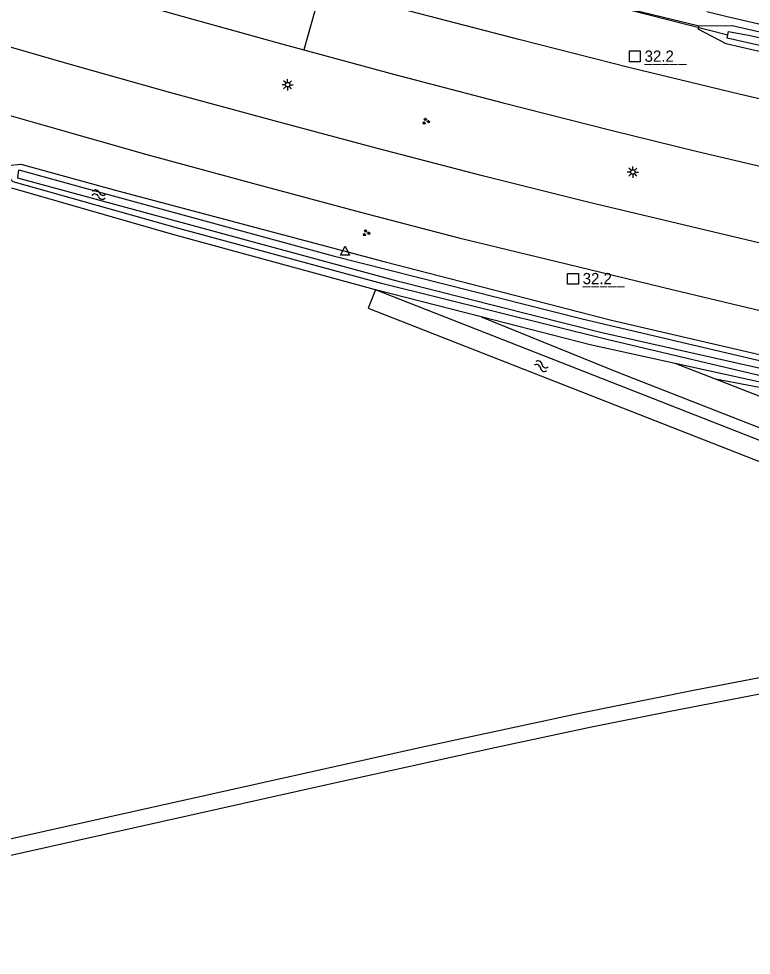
# Model space of a CAD drawing. Extents: x 130998 to 133001, y 398999 to 403002.
# Drawn here: x 131607.2 to 131688.7, y 400571.1 to 400675.3 of the extents above; entities that cross this region are included whole.
import ezdxf

# ---------------------------------------------------------------- set-up
doc = ezdxf.new("R2010")
doc.units = 0
for name, color, linetype in [('gg-afsc-hekwerk', 7, 'Continuous'), ('gg-knt-onverhard', 7, 'Continuous'), ('gg-knt-verharding', 7, 'Continuous'), ('gg-kntw-bovenkant insteek waterloop', 7, 'Continuous'), ('gg-kntw-waterlijn', 7, 'Continuous'), ('gg-kwrk-duiker nz buis', 7, 'Continuous'), ('gt-anno-nummer hm paal', 7, 'Continuous'), ('gt-grn-groengrens', 7, 'Continuous'), ('gt-grn-weggrens', 7, 'Continuous'), ('gt-symb-groenvak', 7, 'Continuous'), ('gt-symb-hm paal', 7, 'Continuous'), ('gt-symb-lichtmast', 7, 'Continuous'), ('gt-symb-waterafsluiter', 7, 'Continuous'), ('gt-symb-watersymbool', 7, 'Continuous')]:
    doc.layers.add(name, color=color, linetype=linetype)

# ---------------------------------------------------------------- blocks, each defined once
blk = doc.blocks.new('gt0-WA')
at = {"layer": 'gt-symb-watersymbool'}
for centre, start, end in [((-0.32, 0.02), 28.0725, 151.9275), ((0.43, 0.42), 208.0725, 331.9275), ((-0.32, -0.43), 28.0725, 151.9275), ((0.43, -0.03), 208.0725, 331.9275)]:
    blk.add_arc(centre, 0.425, start, end, dxfattribs=at)
blk = doc.blocks.new('gt0-HMpaal')
at = {"layer": 'gt-symb-hm paal'}
blk.add_lwpolyline([(-0.6, 0.6), (0.6, 0.6), (0.6, -0.6), (-0.6, -0.6)], close=True, dxfattribs=at)
blk = doc.blocks.new('gt0-WAFSL')
at = {"layer": 'gt-symb-waterafsluiter'}
for p, q in [((-0.5, -0.33), (0, 0.67)), ((0, 0.67), (0.5, -0.33)), ((0.5, -0.33), (-0.5, -0.33))]:
    blk.add_line(p, q, dxfattribs=at)
blk = doc.blocks.new('gt0-GRVAK')
at = {"layer": 'gt-symb-groenvak'}
for p, q in [((-0.11, 0.19), (-0.23, 0.24)), ((-0.18, 0.15), (0.09, 0.15)), ((-0.09, 0.21), (-0.16, 0.32)), ((-0.05, 0.21), (-0.05, 0.39)), ((0, 0.21), (0.06, 0.32)), ((0.01, 0.19), (0.13, 0.24)), ((0.26, -0.05), (0.2, 0.06)), ((0.3, -0.05), (0.3, 0.13)), ((0.35, -0.05), (0.41, 0.06)), ((-0.24, -0.23), (-0.36, -0.18)), ((-0.32, -0.26), (-0.05, -0.26)), ((-0.23, -0.21), (-0.29, -0.09)), ((-0.18, -0.2), (-0.18, -0.02)), ((-0.14, -0.21), (-0.07, -0.09)), ((-0.12, -0.23), (0, -0.18)), ((0.24, -0.07), (0.12, -0.02)), ((0.17, -0.11), (0.44, -0.11)), ((0.37, -0.07), (0.49, -0.02))]:
    blk.add_line(p, q, dxfattribs=at)
blk = doc.blocks.new('gt0-LMAST')
at = {"layer": 'gt-symb-lichtmast'}
for p, q in [((-0.18, 0.17), (-0.45, 0.44)), ((-0.01, 0.25), (-0.01, 0.62)), ((0.17, 0.17), (0.44, 0.44)), ((-0.26, 0), (-0.63, 0)), ((-0.18, -0.18), (-0.45, -0.45)), ((-0.01, -0.25), (-0.01, -0.63)), ((0.44, -0.45), (0.17, -0.18)), ((0.24, 0), (0.62, 0))]:
    blk.add_line(p, q, dxfattribs=at)
blk.add_circle((-0.01, 0), 0.25, dxfattribs=at)

msp = doc.modelspace()

# ---------------------------------------------------------------- linework, layer by layer
at = {"layer": 'gg-afsc-hekwerk'}
msp.add_line((131658.61, 400642.11), (131646.85, 400645.12), dxfattribs=at)
for points in [[(131950.27, 400635.56), (131925.14, 400636.47), (131880.43, 400641.03), (131850.99, 400644.68), (131821.15, 400648.92), (131785.88, 400654.67), (131756.28, 400660.17), (131715.19, 400668.76), (131685.98, 400675.5), (131683.72, 400676.07)], [(131646.85, 400645.12), (131624.28, 400651.3), (131606.38, 400656.43)], [(131680.2, 400636.93), (131670.72, 400639.02), (131658.61, 400642.11)], [(131946.29, 400599.66), (131943.06, 400599.63), (131922.16, 400600.59), (131898.48, 400602.5), (131877.55, 400604.42), (131856.73, 400606.57), (131836.03, 400609.15), (131815.02, 400611.91), (131791.35, 400615.45), (131767.9, 400619.5), (131747.19, 400623.19), (131726.45, 400627.06), (131697.21, 400633.18), (131680.2, 400636.93)]]:
    msp.add_lwpolyline(points, dxfattribs=at)
at = {"layer": 'gg-knt-onverhard'}
for p, q in [((131684.67, 400635.19), (131680.2, 400636.93)), ((131828.74, 400579.08), (131684.67, 400635.19))]:
    msp.add_line(p, q, dxfattribs=at)
for points in [[(131658.61, 400642.11), (131673.88, 400635.94), (131717.7, 400618.81)], [(131448.4, 400549.29), (131470.33, 400553.93), (131480.4, 400556.1), (131504.78, 400561.61), (131533.92, 400567.92), (131548.57, 400571.16), (131573.51, 400576.76), (131651.93, 400594.23), (131669.53, 400598.02), (131682.22, 400600.58), (131695.97, 400603.22), (131700.33, 400603.57), (131704.28, 400604.22), (131705.82, 400604.54), (131708.72, 400605.3), (131710.33, 400605.8), (131712.22, 400606.46), (131714.08, 400607.2), (131715.43, 400607.78), (131718.75, 400609.24)], [(131719.82, 400608.13), (131715.98, 400606.43), (131714.51, 400605.81), (131712.65, 400605.08), (131710.76, 400604.42), (131709.02, 400603.88), (131707.09, 400603.36), (131705.14, 400602.91), (131702.85, 400602.49), (131696.33, 400601.44), (131679.64, 400598.22), (131670.9, 400596.45), (131660.13, 400594.17), (131641.61, 400590.08), (131539.2, 400567.22), (131510.35, 400560.97), (131480.79, 400554.32), (131470.72, 400552.15), (131446.84, 400547.1)]]:
    msp.add_lwpolyline(points, dxfattribs=at)
at = {"layer": 'gg-knt-verharding'}
for points in [[(131606.45, 400681.07), (131612.48, 400679.29), (131624.11, 400675.93), (131636.53, 400672.46), (131638.86, 400671.83)], [(131852.73, 400636.21), (131838.32, 400638.19), (131823.4, 400640.39), (131807.97, 400642.82), (131797.47, 400644.55), (131787, 400646.35), (131776.59, 400648.2), (131766.23, 400650.1), (131755.6, 400652.13), (131745, 400654.22), (131734.47, 400656.37), (131724, 400658.58), (131711.74, 400661.26), (131699.51, 400664.03), (131687.33, 400666.89), (131675.2, 400669.85), (131662.93, 400672.94), (131650.78, 400676.11), (131640.81, 400678.8)], [(131858.26, 400621.66), (131847.63, 400622.95), (131835.75, 400624.33), (131824.09, 400625.84), (131812.51, 400627.49), (131800.06, 400629.36), (131788.83, 400631.08), (131776.91, 400633.03), (131764.74, 400635.15), (131753.24, 400637.26), (131741.18, 400639.44), (131729.54, 400641.68), (131717.12, 400644.12), (131705.36, 400646.72), (131693.56, 400649.4), (131670.48, 400654.89), (131658.75, 400657.83), (131647.08, 400660.87), (131635.59, 400663.92), (131624.09, 400667.07), (131612.5, 400670.31), (131604.9, 400672.51)], [(131638.86, 400671.83), (131648.85, 400669.12), (131661.06, 400665.93), (131673.18, 400662.86), (131682.67, 400660.54), (131692.32, 400658.25), (131702.13, 400655.99), (131711.82, 400653.81)], [(131603.43, 400665.31), (131609.93, 400663.45), (131621.42, 400660.2), (131633.17, 400656.99), (131645.19, 400653.77), (131656.14, 400650.91), (131668.12, 400648.03), (131680, 400645.14), (131692.14, 400642.24), (131703.91, 400639.53), (131715.58, 400637), (131727.34, 400634.63), (131750.65, 400630.3), (131774.9, 400625.98), (131785.71, 400624.19), (131810.93, 400620.35), (131823.02, 400618.64), (131834.31, 400617.18), (131846.77, 400615.74)]]:
    msp.add_lwpolyline(points, dxfattribs=at)
at = {"layer": 'gg-kntw-bovenkant insteek waterloop'}
for points in [[(131922.86, 400633.66), (131878.57, 400638.05), (131850.62, 400641.54), (131821.9, 400645.72), (131785.76, 400651.47), (131752.8, 400657.76), (131714.58, 400665.81), (131685.88, 400672.5), (131682.77, 400674.12), (131682.88, 400674.5)], [(131682.88, 400674.5), (131686.54, 400674.53), (131715.01, 400668.02), (131754.86, 400659.5), (131786.03, 400653.89), (131822.02, 400647.82), (131850.79, 400643.69), (131879.19, 400640.24), (131923.2, 400635.79), (131924.03, 400634.82)], [(131727.11, 400627.4), (131697.37, 400633.76), (131672.6, 400639.61), (131647.53, 400645.84), (131624.96, 400651.94), (131606.55, 400657.14), (131605.57, 400658.2), (131605.92, 400658.95)], [(131605.92, 400658.95), (131607.38, 400659.1), (131618.18, 400656.15), (131647.94, 400648.24), (131673.1, 400641.74), (131697.4, 400636.11), (131723.39, 400630.66)], [(131646.85, 400645.12), (131646.05, 400643.08), (131717.2, 400615.18), (131718, 400617.23), (131646.85, 400645.12)]]:
    msp.add_lwpolyline(points, dxfattribs=at)
at = {"layer": 'gg-kntw-waterlijn'}
for points in [[(131686.12, 400673.87), (131688.53, 400673.42), (131726.5, 400664.89), (131758.93, 400658.08), (131784.42, 400653.45), (131814.56, 400648.5), (131838.39, 400644.88), (131872.87, 400640.36), (131897.84, 400637.8), (131919.8, 400635.54), (131919.7, 400634.55), (131896.67, 400636.92), (131865.02, 400640.54), (131826.97, 400645.74), (131799.53, 400650.1), (131782.74, 400652.76), (131767.96, 400655.48), (131734, 400662.36), (131717.63, 400665.95), (131706.02, 400668.62), (131685.97, 400673.13), (131686.12, 400673.87)], [(131851.22, 400608.39), (131829.22, 400611.22), (131766.55, 400621.07), (131730.07, 400627.67), (131708.11, 400632.21), (131671.89, 400640.4), (131649.26, 400646.1), (131607.06, 400657.55), (131607.18, 400658.47)], [(131607.18, 400658.47), (131616.83, 400655.83), (131642.15, 400648.91), (131669.85, 400641.91), (131694.48, 400636.1), (131723.32, 400630.01), (131754.41, 400624.07), (131794.4, 400617.51), (131813.42, 400614.39), (131835.94, 400611.44), (131858.01, 400608.77)]]:
    msp.add_lwpolyline(points, dxfattribs=at)
at = {"layer": 'gg-kwrk-duiker nz buis'}
msp.add_line((131671.03, 400677.32), (131686.05, 400673.5), dxfattribs=at)
at = {"layer": 'gt-grn-groengrens'}
msp.add_line((131672.33, 400677.06), (131682.88, 400674.5), dxfattribs=at)
msp.add_lwpolyline([(131828.74, 400579.08), (131830.17, 400580.82), (131691.71, 400633.86), (131684.67, 400635.19)], dxfattribs=at)
at = {"layer": 'gt-grn-weggrens'}
msp.add_line((131640.81, 400678.8), (131638.86, 400671.83), dxfattribs=at)

# ---------------------------------------------------------------- block references
at = {"layer": 'gt-symb-groenvak'}
for p in [(131652.45, 400663.89), (131645.81, 400651.47)]:
    msp.add_blockref('gt0-GRVAK', p, dxfattribs=at)
at = {"layer": 'gt-symb-hm paal'}
for p in [(131675.71, 400671.11), (131668.82, 400646.36)]:
    msp.add_blockref('gt0-HMpaal', p, dxfattribs=at)
at = {"layer": 'gt-symb-lichtmast'}
for p in [(131637.08, 400667.96), (131675.5, 400658.24)]:
    msp.add_blockref('gt0-LMAST', p, dxfattribs=at)
at = {"layer": 'gt-symb-waterafsluiter'}
msp.add_blockref('gt0-WAFSL', (131643.47, 400649.32), dxfattribs=at)
at = {"layer": 'gt-symb-watersymbool'}
for p, rotation in [((131616.02, 400655.74), -10.4330247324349), ((131665.23, 400636.67), -23.07822140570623)]:
    msp.add_blockref('gt0-WA', p, dxfattribs=dict(at, rotation=rotation))

# ---------------------------------------------------------------- texts
at = {"layer": 'gt-anno-nummer hm paal'}
for p in [(131676.79, 400670.51), (131669.9, 400645.76)]:
    msp.add_text('32.2', height=1.25, dxfattribs=at).set_placement(p)
at = {"layer": 'gt-symb-hm paal'}
for p in [(131676.79, 400670.51), (131669.9, 400645.76)]:
    msp.add_text('_____', height=1.25, dxfattribs=at).set_placement(p)

doc.saveas('drawing.dxf')
